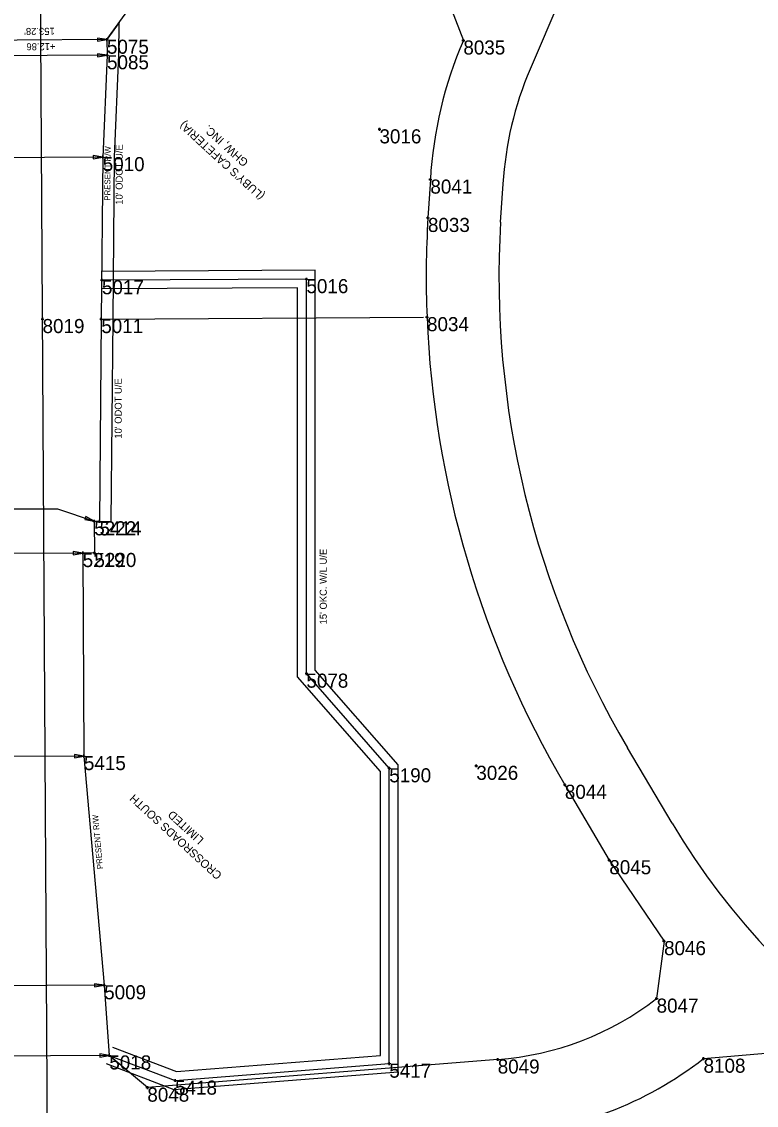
# Model space of a CAD drawing. Extents: x 2145146 to 2158053, y 137507 to 150829.
# Drawn here: x 2150894 to 2151520, y 143925 to 144848 of the extents above; entities that cross this region are included whole.
import ezdxf

# ---------------------------------------------------------------- set-up
doc = ezdxf.new("R2010")
doc.units = 0
for name, color, linetype in [('ALIGN_Cogo Points', 7, 'Continuous'), ('ALIGN_ROW Dimension', 7, 'Continuous'), ('ALIGN_ROW Line', 7, 'Continuous'), ('ALIGN_ROW Text', 7, 'Continuous'), ('PLSS_Easement', 7, 'Continuous'), ('PLSS_Property Line', 7, 'Continuous'), ('PLSS_Section Line', 7, 'Continuous'), ('PLSS_Text', 7, 'Continuous'), ('PLSS_Text_TURNED OFF', 7, 'Continuous')]:
    doc.layers.add(name, color=color, linetype=linetype)

# ---------------------------------------------------------------- blocks, each defined once
blk = doc.blocks.new('Arrowhd')
at = {"layer": 'PLSS_Property Line'}
blk.add_lwpolyline([(0.125, -0.021), (0.125, 0.021), (0, 0)], close=True, dxfattribs=at)

msp = doc.modelspace()

# ---------------------------------------------------------------- linework, layer by layer
at = {"layer": 'ALIGN_Cogo Points'}
for points in [[(2150966.92, 144832.96), (2150966.92, 144834.16), (2150966.92, 144832.96), (2150965.72, 144832.96), (2150966.92, 144832.96), (2150966.92, 144831.76), (2150966.92, 144832.96), (2150968.12, 144832.96)], [(2151270.67, 144832.3), (2151270.67, 144833.5), (2151270.67, 144832.3), (2151269.47, 144832.3), (2151270.67, 144832.3), (2151270.67, 144831.1), (2151270.67, 144832.3), (2151271.87, 144832.3)], [(2150967.01, 144819.7), (2150967.01, 144820.9), (2150967.01, 144819.7), (2150965.81, 144819.7), (2150967.01, 144819.7), (2150967.01, 144818.5), (2150967.01, 144819.7), (2150968.21, 144819.7)], [(2151199.18, 144756.57), (2151199.18, 144757.77), (2151199.18, 144756.57), (2151197.98, 144756.57), (2151199.18, 144756.57), (2151199.18, 144755.37), (2151199.18, 144756.57), (2151200.38, 144756.57)], [(2150963.34, 144732.92), (2150963.34, 144734.12), (2150963.34, 144732.92), (2150962.14, 144732.92), (2150963.34, 144732.92), (2150963.34, 144731.72), (2150963.34, 144732.92), (2150964.54, 144732.92)], [(2151242.55, 144713.73), (2151242.55, 144714.93), (2151242.55, 144713.73), (2151241.35, 144713.73), (2151242.55, 144713.73), (2151242.55, 144712.53), (2151242.55, 144713.73), (2151243.75, 144713.73)], [(2151240.48, 144681.07), (2151240.48, 144682.27), (2151240.48, 144681.07), (2151239.28, 144681.07), (2151240.48, 144681.07), (2151240.48, 144679.87), (2151240.48, 144681.07), (2151241.68, 144681.07)], [(2151136.95, 144628.92), (2151136.95, 144630.12), (2151136.95, 144628.92), (2151135.75, 144628.92), (2151136.95, 144628.92), (2151136.95, 144627.72), (2151136.95, 144628.92), (2151138.15, 144628.92)], [(2150962.68, 144627.99), (2150962.68, 144629.19), (2150962.68, 144627.99), (2150961.48, 144627.99), (2150962.68, 144627.99), (2150962.68, 144626.79), (2150962.68, 144627.99), (2150963.88, 144627.99)], [(2150912.09, 144594.9), (2150912.09, 144596.1), (2150912.09, 144594.9), (2150910.89, 144594.9), (2150912.09, 144594.9), (2150912.09, 144593.7), (2150912.09, 144594.9), (2150913.29, 144594.9)], [(2150962.14, 144594.9), (2150962.14, 144596.1), (2150962.14, 144594.9), (2150960.94, 144594.9), (2150962.14, 144594.9), (2150962.14, 144593.7), (2150962.14, 144594.9), (2150963.34, 144594.9)], [(2151239.69, 144596.5), (2151239.69, 144597.7), (2151239.69, 144596.5), (2151238.49, 144596.5), (2151239.69, 144596.5), (2151239.69, 144595.3), (2151239.69, 144596.5), (2151240.89, 144596.5)], [(2150956.11, 144422.54), (2150956.11, 144423.74), (2150956.11, 144422.54), (2150954.91, 144422.54), (2150956.11, 144422.54), (2150956.11, 144421.34), (2150956.11, 144422.54), (2150957.31, 144422.54)], [(2150960.63, 144422.47), (2150960.63, 144423.67), (2150960.63, 144422.47), (2150959.43, 144422.47), (2150960.63, 144422.47), (2150960.63, 144421.27), (2150960.63, 144422.47), (2150961.83, 144422.47)], [(2150946.27, 144395.48), (2150946.27, 144396.68), (2150946.27, 144395.48), (2150945.07, 144395.48), (2150946.27, 144395.48), (2150946.27, 144394.28), (2150946.27, 144395.48), (2150947.47, 144395.48)], [(2150956.27, 144395.54), (2150956.27, 144396.74), (2150956.27, 144395.54), (2150955.07, 144395.54), (2150956.27, 144395.54), (2150956.27, 144394.34), (2150956.27, 144395.54), (2150957.47, 144395.54)], [(2151136.93, 144292.7), (2151136.93, 144293.9), (2151136.93, 144292.7), (2151135.73, 144292.7), (2151136.93, 144292.7), (2151136.93, 144291.5), (2151136.93, 144292.7), (2151138.13, 144292.7)], [(2150947.31, 144222.48), (2150947.31, 144223.68), (2150947.31, 144222.48), (2150946.11, 144222.48), (2150947.31, 144222.48), (2150947.31, 144221.28), (2150947.31, 144222.48), (2150948.51, 144222.48)], [(2151281.72, 144214.16), (2151281.72, 144215.36), (2151281.72, 144214.16), (2151280.52, 144214.16), (2151281.72, 144214.16), (2151281.72, 144212.96), (2151281.72, 144214.16), (2151282.92, 144214.16)], [(2151207.53, 144212.04), (2151207.53, 144213.24), (2151207.53, 144212.04), (2151206.33, 144212.04), (2151207.53, 144212.04), (2151207.53, 144210.84), (2151207.53, 144212.04), (2151208.73, 144212.04)], [(2151357.18, 144197.97), (2151357.18, 144199.17), (2151357.18, 144197.97), (2151355.98, 144197.97), (2151357.18, 144197.97), (2151357.18, 144196.77), (2151357.18, 144197.97), (2151358.38, 144197.97)], [(2151395.05, 144133.71), (2151395.05, 144134.91), (2151395.05, 144133.71), (2151393.85, 144133.71), (2151395.05, 144133.71), (2151395.05, 144132.51), (2151395.05, 144133.71), (2151396.25, 144133.71)], [(2151441.71, 144064.76), (2151441.71, 144065.96), (2151441.71, 144064.76), (2151440.51, 144064.76), (2151441.71, 144064.76), (2151441.71, 144063.56), (2151441.71, 144064.76), (2151442.91, 144064.76)], [(2150964.59, 144027.13), (2150964.59, 144028.33), (2150964.59, 144027.13), (2150963.39, 144027.13), (2150964.59, 144027.13), (2150964.59, 144025.93), (2150964.59, 144027.13), (2150965.79, 144027.13)], [(2151435.35, 144015.75), (2151435.35, 144016.95), (2151435.35, 144015.75), (2151434.15, 144015.75), (2151435.35, 144015.75), (2151435.35, 144014.55), (2151435.35, 144015.75), (2151436.55, 144015.75)], [(2150968.98, 143967.36), (2150968.98, 143968.56), (2150968.98, 143967.36), (2150967.78, 143967.36), (2150968.98, 143967.36), (2150968.98, 143966.16), (2150968.98, 143967.36), (2150970.18, 143967.36)], [(2151299.95, 143963.89), (2151299.95, 143965.09), (2151299.95, 143963.89), (2151298.75, 143963.89), (2151299.95, 143963.89), (2151299.95, 143962.69), (2151299.95, 143963.89), (2151301.15, 143963.89)], [(2151475.36, 143964.57), (2151475.36, 143965.77), (2151475.36, 143964.57), (2151474.16, 143964.57), (2151475.36, 143964.57), (2151475.36, 143963.37), (2151475.36, 143964.57), (2151476.56, 143964.57)], [(2151207.58, 143960.33), (2151207.58, 143961.53), (2151207.58, 143960.33), (2151206.38, 143960.33), (2151207.58, 143960.33), (2151207.58, 143959.13), (2151207.58, 143960.33), (2151208.78, 143960.33)], [(2151025.02, 143945.87), (2151025.02, 143947.07), (2151025.02, 143945.87), (2151023.82, 143945.87), (2151025.02, 143945.87), (2151025.02, 143944.67), (2151025.02, 143945.87), (2151026.22, 143945.87)], [(2151001.37, 143939.89), (2151001.37, 143941.09), (2151001.37, 143939.89), (2151000.17, 143939.89), (2151001.37, 143939.89), (2151001.37, 143938.69), (2151001.37, 143939.89), (2151002.57, 143939.89)]]:
    msp.add_lwpolyline(points, dxfattribs=at)
at = {"layer": 'ALIGN_ROW Dimension'}
for points in [[(2150966.92, 144832.96), (2150813.65, 144832.04)], [(2150967.01, 144819.7), (2150813.73, 144818.78)], [(2150963.34, 144732.92), (2150814.25, 144732.02)], [(2150816.1, 144421.7), (2150834.77, 144433.03), (2150924.67, 144433.22), (2150956.11, 144422.54)], [(2150946.27, 144395.48), (2150816.28, 144394.69)], [(2150947.31, 144222.48), (2150817.32, 144221.7)], [(2150964.59, 144027.13), (2150818.49, 144026.25)], [(2150968.98, 143967.36), (2150818.85, 143966.46)]]:
    msp.add_lwpolyline(points, dxfattribs=at)
at = {"layer": 'ALIGN_ROW Line'}
msp.add_lwpolyline([(2150966.92, 144832.96), (2150967.01, 144819.7), (2150963.34, 144732.92), (2150962.14, 144594.9), (2150960.63, 144422.47), (2150956.11, 144422.54), (2150956.27, 144395.54), (2150946.27, 144395.48), (2150947.31, 144222.48), (2150964.59, 144027.13), (2150968.98, 143967.36)], dxfattribs=at)
at = {"layer": 'PLSS_Easement'}
msp.add_lwpolyline([(2150960.63, 144422.47), (2150970.63, 144422.34), (2150972.14, 144594.95), (2150973.34, 144732.98), (2150977.02, 144819.89), (2150977.41, 144847.56), (2150966.92, 144832.96), (2150967.01, 144819.7), (2150963.34, 144732.92), (2150962.14, 144594.9)], close=True, dxfattribs=at)
for points in [[(2150966.29, 143960.36), (2151023.92, 143938.26), (2151215.08, 143953.41), (2151215.03, 144214.86), (2151144.43, 144295.52), (2151144.45, 144636.46), (2150962.64, 144635.49)], [(2150968.98, 143967.36), (2151025.02, 143945.87), (2151207.58, 143960.33), (2151207.53, 144212.04), (2151136.93, 144292.7), (2151136.95, 144628.92), (2150962.68, 144627.99)], [(2150971.66, 143974.36), (2151026.12, 143953.49), (2151200.08, 143967.26), (2151200.03, 144209.22), (2151129.43, 144289.88), (2151129.45, 144621.38), (2150962.72, 144620.49)]]:
    msp.add_lwpolyline(points, dxfattribs=at)
at = {"layer": 'PLSS_Property Line'}
for p, q in [((2151385.43, 144943.51), (2151327.59, 144807.73)), ((2151302.37, 144677.42), (2151304.45, 144710.13)), ((2151448.69, 144165.33), (2151410.58, 144229.48))]:
    msp.add_line(p, q, dxfattribs=at)
for points in [[(2150966.92, 144832.96), (2151003.22, 144883.54), (2151198.4, 144884.72), (2151198.4, 144884.72)], [(2151255.84, 144871.52), (2151255.84, 144871.52), (2151270.67, 144832.3)], [(2151242.55, 144713.73), (2151240.48, 144681.07)], [(2150962.14, 144594.9), (2151236.67, 144596.48)], [(2151357.18, 144197.97), (2151357.18, 144197.97), (2151395.05, 144133.71), (2151441.71, 144064.76), (2151435.35, 144015.75), (2151435.35, 144015.75)], [(2151299.95, 143963.89), (2151299.95, 143963.89), (2151001.37, 143939.89), (2150968.98, 143967.36)], [(2151475.36, 143964.57), (2151475.36, 143964.57), (2151531.48, 143969.57)]]:
    msp.add_lwpolyline(points, dxfattribs=at)
for centre, radius, start, end in [((2151592.49, 144693.38), 350.53, 156.65256, 176.67184), ((2151592.49, 144693.38), 288.53, 156.65256, 176.67184), ((2152091.04, 144630.89), 852.04, 176.624, 182.31364), ((2152091.04, 144630.89), 790.04, 176.624, 210.53729), ((2152091.04, 144630.89), 852.04, 182.31364, 210.53729), ((2151975.89, 144476.64), 612.26, 210.56227, 263.37366), ((2151281.72, 144214.16), 250.93, 274.1663, 307.7519), ((2151281.72, 144214.16), 315.9, 274.09802, 307.80598)]:
    msp.add_arc(centre, radius, start, end, dxfattribs=at)
at = {"layer": 'PLSS_Section Line'}
msp.add_lwpolyline([(2150921.68, 142997.28), (2150905.82, 145638.98)], dxfattribs=at)

# ---------------------------------------------------------------- block references
at = {"layer": 'ALIGN_ROW Dimension'}
for p, xscale, yscale, rotation in [((2150966.92, 144832.96), 65.00000000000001, 64.99999999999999, -179.65177652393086), ((2150967.01, 144819.7), 65.00000000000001, 64.99999999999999, -179.65177652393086), ((2150963.34, 144732.92), 65.00000000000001, 64.99999999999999, -179.65177652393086), ((2150956.11, 144422.54), 65, 65, 160.74085774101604), ((2150946.27, 144395.48), 65.00000000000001, 64.99999999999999, -179.65177652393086), ((2150947.31, 144222.48), 65.00000000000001, 64.99999999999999, -179.65177652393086), ((2150964.59, 144027.13), 65.00000000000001, 64.99999999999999, -179.65177652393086), ((2150968.98, 143967.36), 65.00000000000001, 64.99999999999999, -179.65177652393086)]:
    msp.add_blockref('Arrowhd', p, dxfattribs=dict(at, xscale=xscale, yscale=yscale, rotation=rotation))

# ---------------------------------------------------------------- texts
at = {"layer": 'ALIGN_Cogo Points'}
for s, p in [('5075', (2150966.92, 144820.96)), ('8035', (2151270.67, 144820.3)), ('5085', (2150967.01, 144807.7)), ('3016', (2151199.18, 144744.57)), ('5010', (2150963.34, 144720.92)), ('8041', (2151242.55, 144701.73)), ('8033', (2151240.48, 144669.07)), ('5017', (2150962.68, 144615.99)), ('5016', (2151136.95, 144616.92)), ('8019', (2150912.09, 144582.9)), ('5011', (2150962.14, 144582.9)), ('8034', (2151239.69, 144584.5)), ('5222', (2150956.11, 144410.54)), ('5414', (2150960.63, 144410.47)), ('5219', (2150946.27, 144383.48)), ('5220', (2150956.27, 144383.54)), ('5078', (2151136.93, 144280.7)), ('5415', (2150947.31, 144210.48)), ('3026', (2151281.72, 144202.16)), ('5190', (2151207.53, 144200.04)), ('8044', (2151357.18, 144185.97)), ('8045', (2151395.05, 144121.71)), ('8046', (2151441.71, 144052.76)), ('5009', (2150964.59, 144015.13)), ('8047', (2151435.35, 144003.75)), ('5018', (2150968.98, 143955.36)), ('5417', (2151207.58, 143948.33)), ('8049', (2151299.95, 143951.89)), ('8108', (2151475.36, 143952.57)), ('8048', (2151001.37, 143927.89)), ('5418', (2151025.02, 143933.87))]:
    msp.add_text(s, height=12, dxfattribs=at).set_placement(p)
at = {"layer": 'ALIGN_ROW Dimension'}
for s, p in [("153.28'", (2150922.44, 144843.11)), ('+12.86', (2150923.09, 144830.06))]:
    msp.add_text(s, height=6, rotation=180.3718, dxfattribs=at).set_placement(p)
at = {"layer": 'ALIGN_ROW Text'}
for rotation, p in [(89.59405, (2150969.77, 144695.7)), (95.21232, (2150963.59, 144126.32))]:
    msp.add_text('PRESENT R/W', height=5, rotation=rotation, dxfattribs=at).set_placement(p)
at = {"layer": 'PLSS_Text'}
for s, p in [("10' ODOT U/E", (2150980.34, 144692.31)), ("10' ODOT U/E", (2150979.54, 144492.91)), ("15' OKC. W/L U/E", (2151154.29, 144334.63))]:
    msp.add_text(s, height=6, rotation=90, dxfattribs=at).set_placement(p)
at = {"layer": 'PLSS_Text_TURNED OFF'}
for s, p in [("(LUBY'S CAFETERIA)", (2151101.83, 144700.68)), ('GHW, INC.', (2151088.02, 144729.19)), ('CROSSROADS SOUTH', (2151065.49, 144121.66)), ('LIMITED ', (2151050.02, 144151.69))]:
    msp.add_text(s, height=7, rotation=137.49751, dxfattribs=at).set_placement(p)

doc.saveas('drawing.dxf')
